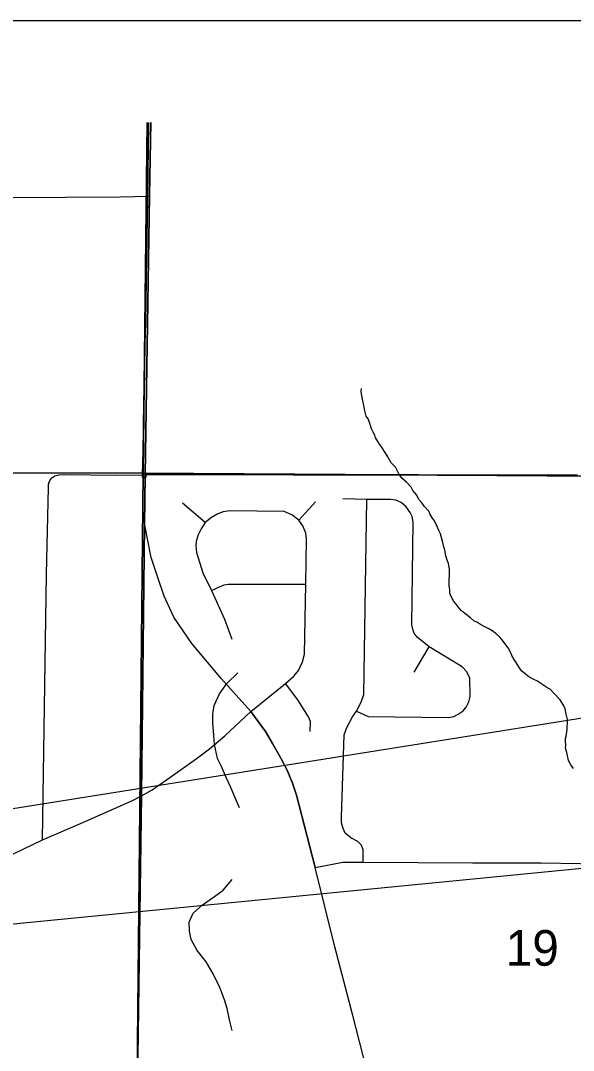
# Model space of a CAD drawing. Extents: x 0 to 34, y 0 to 22.
# Drawn here: x 5.951 to 6.6, y 16.112 to 17.321 of the extents above; entities that cross this region are included whole.
import ezdxf

# ---------------------------------------------------------------- set-up
doc = ezdxf.new("R2010")
doc.units = 0
for name, color, linetype in [('GM_X_City_Street', 7, 'Continuous'), ('GM_X_County_Road', 7, 'Continuous'), ('GM_X_Interchange_Ramps', 7, 'Continuous'), ('GM_X_Interstate_Route', 7, 'Continuous'), ('GM_X_Minor_River', 7, 'Continuous'), ('GM_X_Section', 7, 'Continuous'), ('GM_X_Section_Text', 7, 'Continuous'), ('GM_X_Township_Road', 7, 'Continuous'), ('SH_Data', 7, 'Continuous'), ('SH_Text', 7, 'Continuous')]:
    doc.layers.add(name, color=color, linetype=linetype)

msp = doc.modelspace()

# ---------------------------------------------------------------- linework, layer by layer
at = {"layer": 'GM_X_City_Street'}
for p, q in [((6.0677, 17.1144), (6.1021, 17.115)), ((6.0638, 16.7877), (6.0973, 16.7879)), ((6.1675, 16.732), (6.1409, 16.7545)), ((6.2774, 16.7348), (6.2971, 16.7562)), ((6.4129, 16.5564), (6.4305, 16.5861))]:
    msp.add_line(p, q, dxfattribs=at)
for points in [[(5.9763, 16.3595), (5.9813, 16.6713), (5.9834, 16.773), (5.9837, 16.7771), (5.9852, 16.7812), (5.9876, 16.7843), (5.9911, 16.7868), (5.9957, 16.788), (6.0018, 16.7884), (6.0638, 16.7877)], [(6.3529, 16.3333), (6.353, 16.3478), (6.3511, 16.3531), (6.3466, 16.3574), (6.3385, 16.3618), (6.3319, 16.3674), (6.3294, 16.3727), (6.3276, 16.3794), (6.3276, 16.3862), (6.3305, 16.4826), (6.3336, 16.4912), (6.3405, 16.5037), (6.3453, 16.5106), (6.3507, 16.5209), (6.3537, 16.53), (6.3574, 16.7591)], [(6.3453, 16.5106), (6.359, 16.5043), (6.4533, 16.503), (6.4593, 16.5042), (6.4646, 16.5068), (6.4702, 16.5107), (6.474, 16.515), (6.477, 16.5213), (6.4786, 16.5277), (6.4784, 16.5496), (6.4743, 16.5571), (6.4692, 16.5626), (6.4305, 16.5861), (6.4162, 16.5973), (6.4127, 16.6021), (6.4112, 16.6068), (6.41, 16.6119), (6.4118, 16.7322), (6.4105, 16.7391), (6.4082, 16.7437), (6.4035, 16.7502), (6.3976, 16.7553), (6.3915, 16.758), (6.3851, 16.759), (6.3574, 16.7591), (6.3292, 16.7597)], [(6.2211, 16.51), (6.2616, 16.5429), (6.2715, 16.5515), (6.277, 16.5582), (6.2818, 16.5684), (6.2842, 16.5774), (6.2856, 16.6597), (6.2863, 16.7127), (6.2858, 16.7193), (6.282, 16.7281), (6.2774, 16.7348), (6.2693, 16.7408), (6.2604, 16.7447), (6.1959, 16.7455), (6.1887, 16.7445), (6.1824, 16.742), (6.175, 16.738), (6.1675, 16.732), (6.1626, 16.7245), (6.1592, 16.7176), (6.157, 16.7098), (6.1564, 16.7045), (6.1572, 16.6969), (6.1648, 16.6728), (6.1748, 16.6523), (6.1903, 16.6186), (6.1988, 16.5949)], [(6.1748, 16.6523), (6.1841, 16.6564), (6.1897, 16.6586), (6.1943, 16.6594), (6.2856, 16.6597)], [(6.2908, 16.4868), (6.291, 16.4985), (6.2889, 16.5039), (6.2763, 16.5238), (6.2616, 16.5429)]]:
    msp.add_lwpolyline(points, dxfattribs=at)
at = {"layer": 'GM_X_County_Road'}
for points in [[(6.0973, 16.7879), (6.1021, 17.115), (6.104, 17.2013)], [(6.2211, 16.51), (6.1866, 16.5486), (6.1517, 16.5898), (6.1308, 16.6209), (6.1194, 16.6453), (6.1121, 16.6662), (6.1039, 16.6909), (6.0966, 16.729), (6.0973, 16.7879)], [(6.2965, 16.3271), (6.2746, 16.4118), (6.2699, 16.4261), (6.2638, 16.4411), (6.2563, 16.4555), (6.2467, 16.4724), (6.2381, 16.4866), (6.2211, 16.51)], [(6.3648, 16.0601), (6.3409, 16.1531), (6.3198, 16.234), (6.2965, 16.3271)]]:
    msp.add_lwpolyline(points, dxfattribs=at)
at = {"layer": 'GM_X_Interchange_Ramps'}
for points in [[(6.6048, 16.7874), (6.582, 16.7874), (6.5715, 16.7874), (6.4612, 16.7876), (6.443, 16.7877), (6.44, 16.7877), (6.418, 16.7878), (6.4134, 16.7878), (6.3943, 16.7878), (6.3829, 16.7878), (6.3754, 16.7879), (6.3642, 16.7879), (6.3451, 16.7879), (6.3301, 16.7879), (6.3234, 16.7879), (6.3224, 16.7879), (6.3193, 16.7879), (6.3118, 16.7879), (6.3102, 16.7879), (6.3074, 16.7879), (6.2971, 16.788), (6.2937, 16.788), (6.2839, 16.788), (6.2767, 16.788), (6.2706, 16.788), (6.2577, 16.788), (6.2574, 16.7881), (6.2545, 16.7881), (6.2441, 16.7881), (6.2413, 16.7881), (6.2387, 16.7881), (6.2308, 16.7881), (6.228, 16.7881), (6.2197, 16.7881), (6.2176, 16.7882), (6.2147, 16.7882), (6.2062, 16.7882), (6.2043, 16.7882), (6.2007, 16.7882), (6.192, 16.7882), (6.1911, 16.7882), (6.1882, 16.7882), (6.1722, 16.7883), (6.1489, 16.7883), (6.1451, 16.7883), (6.1356, 16.7883), (6.1328, 16.7884), (6.1316, 16.7884), (6.1224, 16.7884), (6.1195, 16.7884), (6.1072, 16.7884), (6.1063, 16.7884), (6.1016, 16.7884), (6.0982, 16.7884), (6.0978, 16.7884), (6.0977, 16.7849), (6.0977, 16.7847), (6.0939, 16.7847), (6.094, 16.7923), (6.0941, 16.7972), (6.0945, 16.8205), (6.0949, 16.8375), (6.095, 16.8459), (6.0955, 16.8716), (6.0961, 16.9086), (6.0968, 16.9459), (6.0969, 16.9511), (6.0976, 16.9888), (6.0981, 17.0184), (6.0998, 17.1129), (6.1011, 17.2013)], [(6.1011, 17.2013), (6.0998, 17.1129), (6.0981, 17.0184), (6.0976, 16.9888), (6.0969, 16.9511), (6.0968, 16.9459), (6.0961, 16.9086), (6.0955, 16.8716), (6.095, 16.8459), (6.0949, 16.8375), (6.0945, 16.8205), (6.0941, 16.7972), (6.094, 16.7923), (6.0939, 16.7847), (6.0977, 16.7847), (6.0977, 16.7849), (6.0978, 16.7884), (6.0982, 16.7884), (6.1016, 16.7884), (6.1063, 16.7884), (6.1072, 16.7884), (6.1195, 16.7884), (6.1224, 16.7884), (6.1316, 16.7884), (6.1356, 16.7884), (6.1451, 16.7883), (6.1489, 16.7883), (6.1722, 16.7883), (6.1882, 16.7882), (6.1911, 16.7882), (6.192, 16.7882), (6.2007, 16.7882), (6.2043, 16.7882), (6.2062, 16.7882), (6.2147, 16.7882), (6.2176, 16.7882), (6.2197, 16.7881), (6.228, 16.7881), (6.2308, 16.7881), (6.2387, 16.7881), (6.2413, 16.7881), (6.2441, 16.7881), (6.2545, 16.7881), (6.2574, 16.7881), (6.2577, 16.7881), (6.2706, 16.788), (6.2767, 16.788), (6.2839, 16.788), (6.2865, 16.788), (6.2937, 16.788), (6.2971, 16.788), (6.3074, 16.7879), (6.3102, 16.7879), (6.3193, 16.7879), (6.3224, 16.7879), (6.3234, 16.7879), (6.3301, 16.7879), (6.3451, 16.7879), (6.3642, 16.7879), (6.3754, 16.7879), (6.3829, 16.7878), (6.3943, 16.7878), (6.4134, 16.7878), (6.418, 16.7878), (6.44, 16.7877), (6.443, 16.7877), (6.4612, 16.7877), (6.5715, 16.7874), (6.582, 16.7874), (6.6048, 16.7874)]]:
    msp.add_lwpolyline(points, dxfattribs=at)
at = {"layer": 'GM_X_Interstate_Route'}
for points in [[(6.1037, 17.2013), (6.1019, 17.1156), (6.0971, 16.7884), (6.0964, 16.7295), (6.0926, 16.4117), (6.0854, 15.8819)], [(6.0854, 15.8819), (6.0926, 16.4117), (6.0964, 16.7295), (6.0971, 16.7884), (6.1019, 17.1156), (6.1037, 17.2013)]]:
    msp.add_lwpolyline(points, dxfattribs=at)
at = {"layer": 'GM_X_Minor_River'}
for points in [[(6.5924, 16.4889), (6.5925, 16.4927), (6.593, 16.4961), (6.5927, 16.5007), (6.5913, 16.5068), (6.59, 16.5133), (6.5885, 16.5168), (6.5841, 16.5237), (6.5763, 16.5319), (6.5726, 16.5362), (6.5696, 16.5374), (6.5663, 16.5398), (6.5614, 16.5429), (6.5569, 16.5461), (6.5532, 16.5477), (6.5494, 16.5497), (6.546, 16.5521), (6.543, 16.5544), (6.539, 16.5579), (6.5356, 16.5626), (6.5327, 16.5676), (6.5301, 16.5711), (6.5276, 16.5757), (6.5262, 16.5788), (6.5233, 16.585), (6.5203, 16.5885), (6.5174, 16.5927), (6.5133, 16.5974), (6.5088, 16.6017), (6.5044, 16.6048), (6.5006, 16.6072), (6.4957, 16.6096), (6.4909, 16.6124), (6.4871, 16.6144), (6.483, 16.6164), (6.4789, 16.6199), (6.4725, 16.625), (6.4684, 16.6282), (6.4644, 16.6328), (6.4622, 16.6359), (6.4596, 16.6394), (6.4563, 16.6452), (6.4549, 16.649), (6.4546, 16.6528), (6.4539, 16.6578), (6.4544, 16.6772), (6.4531, 16.6837), (6.4516, 16.6879), (6.4502, 16.6929), (6.4489, 16.6994), (6.4475, 16.7032), (6.4464, 16.7086), (6.4454, 16.7128), (6.4437, 16.7185), (6.4418, 16.7224), (6.4397, 16.7274), (6.4368, 16.7339), (6.4342, 16.737), (6.4317, 16.7413), (6.4299, 16.7451), (6.4247, 16.7513), (6.4221, 16.7548), (6.4184, 16.7591), (6.4159, 16.7641), (6.4111, 16.7695), (6.4093, 16.7734), (6.4037, 16.7792), (6.3989, 16.7835), (6.3948, 16.7889), (6.3908, 16.7967), (6.386, 16.8021), (6.382, 16.809), (6.3787, 16.8141), (6.3754, 16.8195), (6.3714, 16.8249), (6.3699, 16.828), (6.3673, 16.8315), (6.3666, 16.8345), (6.3648, 16.838), (6.3626, 16.8418), (6.3602, 16.8506), (6.3588, 16.8537), (6.3565, 16.8568), (6.3548, 16.863), (6.3538, 16.8694), (6.3524, 16.8748), (6.3518, 16.879), (6.3511, 16.8828), (6.3508, 16.8859), (6.3509, 16.8893)], [(6.2078, 16.3971), (6.2027, 16.4086), (6.1976, 16.4209), (6.1925, 16.432), (6.1867, 16.4454), (6.1819, 16.455), (6.1785, 16.4715), (6.1776, 16.4825), (6.1763, 16.4966), (6.1765, 16.5072), (6.1779, 16.5171), (6.1843, 16.531), (6.1929, 16.543), (6.2057, 16.5553)], [(6.6, 16.4431), (6.5967, 16.4473), (6.5942, 16.4527), (6.5921, 16.4619), (6.5907, 16.4669), (6.5908, 16.4707), (6.5905, 16.4749), (6.5906, 16.4783), (6.5914, 16.4813), (6.5924, 16.4889)], [(6.199, 16.1356), (6.1962, 16.1482), (6.1931, 16.1616), (6.1902, 16.1715), (6.1848, 16.1861), (6.1768, 16.2022), (6.1687, 16.2161), (6.1579, 16.2296), (6.1509, 16.2423), (6.1489, 16.2522), (6.1487, 16.2629), (6.1535, 16.2734), (6.1643, 16.2831), (6.1783, 16.2931), (6.1887, 16.3005), (6.1992, 16.3128)]]:
    msp.add_lwpolyline(points, dxfattribs=at)
at = {"layer": 'GM_X_Section'}
for points in [[(6.0995, 17.2013), (6.0948, 16.7898), (5.0741, 16.7917), (5.0842, 17.2013)], [(7.0969, 17.2013), (7.0964, 17.1237), (7.0819, 17.0941), (7.0514, 17.0268), (7.021, 16.9376), (6.9932, 16.8495), (6.9844, 16.7838), (6.0948, 16.7898), (6.0995, 17.2013)]]:
    msp.add_lwpolyline(points, dxfattribs=at)
for points in [[(5.0741, 16.7917), (6.0948, 16.7898), (6.0861, 15.9241), (5.7249, 15.8958), (5.3975, 15.7702), (5.0286, 15.7742)], [(6.0948, 16.7898), (6.9844, 16.7838), (6.9873, 16.6152), (6.9972, 16.3935), (7.041, 16.204), (7.0729, 16.1304), (7.1274, 16.0278), (7.1029, 15.7094), (6.5318, 15.7114), (6.5013, 15.7597), (6.4591, 15.7915), (6.392, 15.8507), (6.3125, 15.8931), (6.2572, 15.9127), (6.2022, 15.9262), (6.202, 15.9264), (6.0861, 15.9241)]]:
    msp.add_lwpolyline(points, close=True, dxfattribs=at)
at = {"layer": 'GM_X_Township_Road'}
for points in [[(5.8637, 17.1133), (5.8734, 17.1132), (6.0677, 17.1144)], [(5.9763, 16.3595), (6.0237, 16.3798), (6.0813, 16.4054), (6.0928, 16.4112), (6.1051, 16.418), (6.126, 16.4326), (6.1568, 16.4545), (6.1725, 16.4663), (6.1904, 16.4817), (6.2211, 16.51)], [(6.2211, 16.51), (6.2381, 16.4866), (6.2467, 16.4724), (6.2563, 16.4555), (6.2638, 16.4411), (6.2699, 16.4261), (6.2746, 16.4118), (6.2965, 16.3271)], [(5.2943, 16.2857), (5.4318, 16.285), (5.5785, 16.285), (5.7265, 16.285), (5.7616, 16.2852), (5.7842, 16.2855), (5.7987, 16.2865), (5.8142, 16.2893), (5.8323, 16.2935), (5.8479, 16.2982), (5.8604, 16.3029), (5.8731, 16.3089), (5.889, 16.3167), (5.9303, 16.337), (5.9763, 16.3595)], [(6.2965, 16.3271), (6.3292, 16.3334), (6.3529, 16.3333), (6.4815, 16.3325), (6.5618, 16.3325), (6.6077, 16.3318), (6.6221, 16.3311), (6.6337, 16.3293), (6.6424, 16.3265), (6.6504, 16.3226), (6.6597, 16.3165), (6.6668, 16.3095), (6.6729, 16.3023), (6.6772, 16.2956), (6.6845, 16.278), (6.6918, 16.2514)]]:
    msp.add_lwpolyline(points, dxfattribs=at)
at = {"layer": 'SH_Data'}
msp.add_line((2, 17.3211), (9, 17.3211), dxfattribs=at)
at = {"layer": 'SH_Text'}
msp.add_lwpolyline([(9.6169, 16.9806), (3.7384, 16.0451), (9.6169, 16.6206)], close=True, dxfattribs=at)

# ---------------------------------------------------------------- texts
at = {"layer": 'GM_X_Section_Text'}
msp.add_text('19', height=0.04186, rotation=0, dxfattribs=at).set_placement((6.5204, 16.2117))

doc.saveas('drawing.dxf')
